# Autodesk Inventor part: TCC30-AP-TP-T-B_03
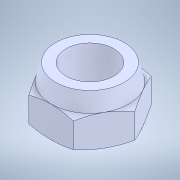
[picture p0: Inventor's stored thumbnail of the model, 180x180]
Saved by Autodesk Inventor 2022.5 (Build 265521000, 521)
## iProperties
Created: 2023-09
Part Number: TCC30-AP-TP-T-B_03
Material: 一般
Document SubType Name: Modeling
Designer: ImaoCorp
Density: 1 g/cm^3
Appearance: 既定
Author: ImaoCorp
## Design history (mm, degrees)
feature "TCC30-AP-TP-T-B_03"
node "ソリッド1"
